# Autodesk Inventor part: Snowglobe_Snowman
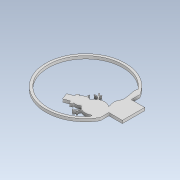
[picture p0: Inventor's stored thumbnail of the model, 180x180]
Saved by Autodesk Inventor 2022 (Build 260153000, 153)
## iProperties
Created: 2021-12
Part Number: Snowglobe_Snowman
Material: Generic
Document SubType Name: Modeling
Designer: allis
Density: 1 g/cm^3
Appearance: Flat - Polished Gray
Author: allis
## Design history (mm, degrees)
sketch "Sketch3"
  geometry: L1 (44.005, -84.208)-(44.235, -84.208); L2 (44.235, -84.208)-(44.36, -84.217); L3 (44.36, -84.217)-(44.483, -84.206); L4 (44.483, -84.206)-(45.37, -84.124); L5 (45.37, -84.124)-(46.233, -83.954); L6 (46.233, -83.954)-(47.079, -83.653); L7 (47.079, -83.653)-(50.349, -82.489); L8 (50.349, -82.489)-(53.524, -82.676); L9 (53.524, -82.676)-(56.593, -84.36); L10 (56.593, -84.36)-(58.068, -85.169); L11 (58.068, -85.169)-(59.646, -85.65); L12 (59.646, -85.65)-(61.344, -85.457); L13 (61.344, -85.457)-(63.838, -85.173); L14 (63.838, -85.173)-(66.306, -84.713); L15 (66.306, -84.713)-(68.77, -84.239); L16 (68.77, -84.239)-(69.959, -84.01); L17 (69.959, -84.01)-(71.088, -83.529); L18 (71.088, -83.529)-(72.305, -83.406); L19 (72.305, -83.406)-(73.785, -83.257); L20 (73.785, -83.257)-(75.239, -83.289); L21 (75.239, -83.289)-(76.605, -83.962); L22 (76.605, -83.962)-(76.917, -84.116); L23 (76.917, -84.116)-(77.13, -84.092); L24 (77.13, -84.092)-(77.396, -83.868); L25 (77.396, -83.868)-(78.791, -82.696); L26 (78.791, -82.696)-(80.127, -81.463); L27 (80.127, -81.463)-(81.374, -80.133); L28 (81.374, -80.133)-(84.658, -76.632); L29 (84.658, -76.632)-(87.287, -72.696); L30 (87.287, -72.696)-(89.202, -68.294); L31 (89.202, -68.294)-(91.842, -62.227); L32 (91.842, -62.227)-(92.971, -55.887); L33 (92.971, -55.887)-(92.619, -49.277); L34 (92.619, -49.277)-(92.476, -46.578); L35 (92.476, -46.578)-(92.094, -43.919); L36 (92.094, -43.919)-(91.429, -41.302); L37 (91.429, -41.302)-(89.464, -33.572); L38 (89.464, -33.572)-(85.609, -26.928); L39 (85.609, -26.928)-(79.852, -21.416); L40 (79.852, -21.416)-(72.332, -14.216); L41 (72.332, -14.216)-(63.334, -10.366); L42 (63.334, -10.366)-(52.953, -9.783); L43 (52.953, -9.783)-(50.049, -9.62); L44 (50.049, -9.62)-(47.147, -9.778); L45 (47.147, -9.778)-(44.267, -10.252); L46 (44.267, -10.252)-(35.108, -11.758); L47 (35.108, -11.758)-(27.274, -15.826); L48 (27.274, -15.826)-(20.836, -22.502); L49 (20.836, -22.502)-(13.443, -30.168); L50 (13.443, -30.168)-(9.59, -39.381); L51 (9.59, -39.381)-(9.101, -50.003); L52 (9.101, -50.003)-(8.982, -52.586); L53 (8.982, -52.586)-(9.147, -55.164); L54 (9.147, -55.164)-(9.53, -57.722); L55 (9.53, -57.722)-(10.376, -63.362); L56 (10.376, -63.362)-(12.282, -68.616); L57 (12.282, -68.616)-(15.282, -73.47); L58 (15.282, -73.47)-(17.571, -77.171); L59 (17.571, -77.171)-(20.379, -80.428); L60 (20.379, -80.428)-(23.67, -83.272); L61 (23.67, -83.272)-(23.844, -83.422); L62 (23.844, -83.422)-(24.018, -83.553); L63 (24.018, -83.553)-(24.271, -83.53); L64 (24.271, -83.53)-(24.818, -83.48)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; 1 further point
  constraints: 2 other
extrude "Extrusion2" new body sketch "Sketch3" distance "d2" = 3.175; taper "d3" = 0 deg
feature "Move Body1"
body "Solid2"
other parameters: "d4" = 90 deg
